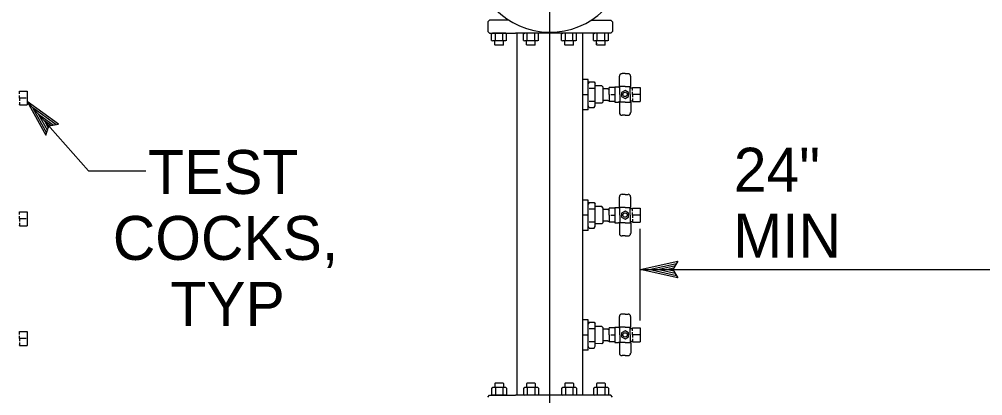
# Model space of a CAD drawing. Extents: x -1680 to 1155, y -802 to 799.
# Drawn here: x 316.4 to 469.8, y -453.1 to -393.2 of the extents above; entities that cross this region are included whole.
import ezdxf

# ---------------------------------------------------------------- set-up
doc = ezdxf.new("R2010")
doc.units = 0
doc.layers.add('Misc CnstDet(22)', color=7, linetype='Continuous')

msp = doc.modelspace()

# ---------------------------------------------------------------- linework, layer by layer
at = {"layer": 'Misc CnstDet(22)'}
for p, q in [((400.86, -548.25), (400.86, -300.3)), ((390.94, -393.62), (391.21, -393.34)), ((390.94, -393.62), (390.94, -395.14)), ((394.3, -393.34), (391.21, -393.34)), ((407.44, -393.34), (410.53, -393.34)), ((410.53, -393.34), (410.8, -393.62)), ((410.8, -393.62), (410.8, -395.14)), ((390.94, -395.14), (391.21, -395.41)), ((391.21, -395.41), (395.35, -395.41)), ((391.56, -395.5), (391.72, -395.41)), ((391.56, -396.56), (391.56, -395.5)), ((393.79, -395.41), (391.72, -395.41)), ((392.16, -396.55), (392.16, -395.51)), ((393.35, -396.55), (393.35, -395.51)), ((393.95, -395.5), (393.79, -395.41)), ((393.95, -396.56), (393.95, -395.5)), ((400.87, -395.41), (395.35, -395.41)), ((395.63, -396.68), (395.63, -395.41)), ((396.64, -395.5), (396.8, -395.41)), ((396.64, -396.56), (396.64, -395.5)), ((398.87, -395.41), (396.8, -395.41)), ((397.23, -396.55), (397.23, -395.51)), ((398.43, -396.55), (398.43, -395.51)), ((399.03, -395.5), (398.87, -395.41)), ((399.03, -396.56), (399.03, -395.5)), ((410.53, -395.41), (400.87, -395.41)), ((402.71, -395.5), (402.87, -395.41)), ((402.71, -396.56), (402.71, -395.5)), ((404.94, -395.41), (402.87, -395.41)), ((403.31, -396.55), (403.31, -395.51)), ((404.51, -396.55), (404.51, -395.51)), ((405.1, -395.5), (404.94, -395.41)), ((405.1, -396.56), (405.1, -395.5)), ((406.11, -396.68), (406.11, -395.41)), ((407.79, -395.5), (407.95, -395.41)), ((407.79, -396.56), (407.79, -395.5)), ((410.02, -395.41), (407.95, -395.41)), ((408.39, -396.55), (408.39, -395.51)), ((409.58, -396.55), (409.58, -395.51)), ((410.18, -395.5), (410.02, -395.41)), ((410.18, -396.56), (410.18, -395.5)), ((410.8, -395.14), (410.53, -395.41)), ((391.56, -396.56), (391.72, -396.65)), ((393.79, -396.65), (391.72, -396.65)), ((392.07, -397.28), (392.07, -396.65)), ((392.13, -397.34), (392.07, -397.28)), ((393.38, -397.34), (393.44, -397.28)), ((393.44, -397.28), (393.44, -396.65)), ((393.95, -396.56), (393.79, -396.65)), ((395.63, -453.08), (395.63, -396.68)), ((396.64, -396.56), (396.8, -396.65)), ((398.87, -396.65), (396.8, -396.65)), ((397.14, -397.28), (397.14, -396.65)), ((397.21, -397.34), (397.14, -397.28)), ((398.46, -397.34), (398.52, -397.28)), ((398.52, -397.28), (398.52, -396.65)), ((399.03, -396.56), (398.87, -396.65)), ((402.71, -396.56), (402.87, -396.65)), ((404.94, -396.65), (402.87, -396.65)), ((403.22, -397.28), (403.22, -396.65)), ((403.28, -397.34), (403.22, -397.28)), ((404.53, -397.34), (404.6, -397.28)), ((404.6, -397.28), (404.6, -396.65)), ((405.1, -396.56), (404.94, -396.65)), ((406.11, -453.08), (406.11, -396.68)), ((407.79, -396.56), (407.95, -396.65)), ((410.02, -396.65), (407.95, -396.65)), ((408.29, -397.28), (408.29, -396.65)), ((408.36, -397.09), (408.29, -397.02)), ((408.36, -397.34), (408.29, -397.28)), ((409.61, -397.34), (409.67, -397.28)), ((409.67, -397.28), (409.67, -396.65)), ((410.18, -396.56), (410.02, -396.65)), ((393.38, -397.34), (392.13, -397.34)), ((398.46, -397.34), (397.21, -397.34)), ((404.53, -397.34), (403.28, -397.34)), ((409.61, -397.34), (408.36, -397.34)), ((412.81, -401.86), (412.33, -401.86)), ((412.81, -401.86), (413.29, -401.86)), ((406.94, -402.79), (406.11, -402.79)), ((406.94, -407.62), (406.94, -402.79)), ((407.1, -403.15), (406.94, -403.42)), ((407.1, -403.15), (407.88, -403.15)), ((407.88, -403.15), (408.04, -403.42)), ((407.97, -403.28), (408.04, -403.41)), ((408.04, -406.99), (408.04, -403.41)), ((408.04, -406.99), (408.04, -403.41)), ((411.92, -403.93), (411.92, -402.28)), ((413.71, -403.93), (413.71, -402.28)), ((316.39, -405.1), (316.39, -404.64)), ((316.39, -404.64), (317.61, -404.64)), ((317.61, -404.64), (317.61, -405.75)), ((407.1, -404.16), (407.88, -404.16)), ((409.11, -403.82), (408.04, -403.82)), ((409.33, -404.04), (409.11, -403.82)), ((409.33, -406.36), (409.33, -404.04)), ((409.54, -404.27), (409.33, -404.28)), ((410.09, -404.27), (409.54, -404.27)), ((410.09, -404.27), (410.3, -404.28)), ((410.3, -405.17), (410.3, -404.07)), ((411.21, -404.07), (410.3, -404.07)), ((410.41, -404.38), (410.41, -404.38)), ((411.21, -404.07), (411.06, -404.07)), ((411.21, -403.97), (411.21, -406.38)), ((411.21, -403.97), (411.76, -403.97)), ((411.81, -403.97), (411.81, -403.97)), ((411.81, -404.07), (411.81, -404)), ((411.84, -404.02), (411.98, -404.02)), ((412.81, -403.93), (411.92, -403.93)), ((411.98, -405.17), (411.98, -403.93)), ((412.81, -403.93), (413.71, -403.93)), ((413.64, -405.17), (413.64, -403.93)), ((413.65, -404.14), (413.96, -404.14)), ((414, -404.52), (414, -404.07)), ((414, -404.07), (415.22, -404.07)), ((414, -405.17), (414, -404.75)), ((415.22, -404.07), (415.22, -405.17)), ((316.39, -405.75), (316.39, -405.32)), ((316.39, -405.75), (316.39, -406.17)), ((316.39, -406.4), (316.39, -406.85)), ((317.48, -405.75), (316.52, -405.75)), ((317.61, -405.75), (317.61, -406.85)), ((322.59, -409.9), (317.61, -406.3)), ((317.61, -406.3), (317.61, -406.3)), ((317.61, -406.3), (320.59, -411.67)), ((406.94, -405.21), (406.11, -405.21)), ((407.1, -406.24), (407.88, -406.24)), ((409.33, -406.36), (409.11, -406.58)), ((409.54, -406.13), (409.33, -406.12)), ((410.09, -406.13), (409.54, -406.13)), ((410.09, -406.13), (410.3, -406.12)), ((410.3, -405.17), (410.3, -406.28)), ((411.21, -406.28), (410.3, -406.28)), ((410.41, -406.23), (410.41, -406.23)), ((410.55, -405.17), (411.21, -405.17)), ((411.21, -406.38), (411.76, -406.38)), ((411.81, -406.28), (411.81, -406.34)), ((411.84, -406.32), (411.98, -406.32)), ((411.92, -406.41), (411.92, -408.07)), ((412.81, -406.41), (411.92, -406.41)), ((411.98, -405.17), (411.98, -406.41)), ((412.81, -406.41), (413.71, -406.41)), ((413.64, -405.17), (413.64, -406.41)), ((413.65, -406.21), (413.96, -406.21)), ((413.71, -406.41), (413.71, -408.07)), ((414, -405.17), (414, -405.6)), ((414, -405.82), (414, -406.28)), ((414, -406.28), (415.22, -406.28)), ((415.09, -405.17), (414.13, -405.17)), ((415.22, -405.17), (415.22, -406.28)), ((316.39, -406.85), (317.61, -406.85)), ((322.18, -409.98), (318.53, -407.33)), ((318.53, -407.34), (320.7, -411.26)), ((406.94, -407.62), (406.11, -407.62)), ((407.1, -407.27), (406.94, -406.99)), ((407.1, -407.27), (407.88, -407.27)), ((407.88, -407.27), (408.04, -406.99)), ((409.11, -406.58), (408.04, -406.58)), ((321.76, -410.04), (319.44, -408.37)), ((319.44, -408.37), (320.85, -410.9)), ((321.38, -410.14), (320.36, -409.4)), ((320.36, -409.4), (320.96, -410.48)), ((412.81, -408.48), (412.33, -408.48)), ((412.81, -408.48), (413.29, -408.48)), ((320.59, -411.67), (321.06, -410.19)), ((321.06, -410.19), (322.59, -409.9)), ((322.59, -409.9), (322.59, -409.9)), ((320.59, -411.67), (320.59, -411.67)), ((411.92, -423.15), (411.92, -421.49)), ((412.81, -421.08), (412.33, -421.08)), ((412.81, -421.08), (413.29, -421.08)), ((413.71, -423.15), (413.71, -421.49)), ((406.94, -422.01), (406.11, -422.01)), ((406.94, -426.84), (406.94, -422.01)), ((407.1, -422.36), (406.94, -422.64)), ((407.1, -422.36), (407.88, -422.36)), ((407.1, -423.38), (407.88, -423.38)), ((407.88, -422.36), (408.04, -422.64)), ((407.97, -422.49), (408.04, -422.62)), ((408.04, -426.21), (408.04, -422.62)), ((408.04, -426.21), (408.04, -422.62)), ((409.11, -423.04), (408.04, -423.04)), ((409.33, -423.26), (409.11, -423.04)), ((409.33, -425.57), (409.33, -423.26)), ((410.3, -424.39), (410.3, -423.29)), ((411.21, -423.29), (410.3, -423.29)), ((411.21, -423.29), (411.06, -423.29)), ((411.21, -423.18), (411.21, -425.59)), ((411.21, -423.18), (411.76, -423.18)), ((411.81, -423.18), (411.81, -423.18)), ((411.81, -423.29), (411.81, -423.22)), ((411.84, -423.24), (411.98, -423.24)), ((412.81, -423.15), (411.92, -423.15)), ((411.98, -424.39), (411.98, -423.15)), ((412.81, -423.15), (413.71, -423.15)), ((413.64, -424.39), (413.64, -423.15)), ((413.65, -423.35), (413.96, -423.35)), ((414, -423.74), (414, -423.29)), ((414, -423.29), (415.22, -423.29)), ((415.22, -423.29), (415.22, -424.39)), ((316.39, -424.31), (316.39, -423.86)), ((316.39, -423.86), (317.61, -423.86)), ((316.39, -424.96), (316.39, -424.54)), ((317.61, -423.86), (317.61, -424.96)), ((406.94, -424.42), (406.11, -424.42)), ((409.54, -423.49), (409.33, -423.49)), ((410.09, -423.49), (409.54, -423.49)), ((410.09, -423.49), (410.3, -423.49)), ((410.3, -424.39), (410.3, -425.49)), ((410.41, -423.59), (410.41, -423.59)), ((410.55, -424.39), (411.21, -424.39)), ((411.98, -424.39), (411.98, -425.63)), ((413.64, -424.39), (413.64, -425.63)), ((414, -424.39), (414, -423.96)), ((414, -424.39), (414, -424.82)), ((415.09, -424.39), (414.13, -424.39)), ((415.22, -424.39), (415.22, -425.49)), ((316.39, -424.96), (316.39, -425.39)), ((316.39, -425.62), (316.39, -426.07)), ((316.39, -426.07), (317.61, -426.07)), ((317.48, -424.96), (316.52, -424.96)), ((317.61, -424.96), (317.61, -426.07)), ((407.1, -426.49), (406.94, -426.21)), ((407.1, -425.45), (407.88, -425.45)), ((407.88, -426.49), (408.04, -426.21)), ((409.11, -425.79), (408.04, -425.79)), ((409.33, -425.57), (409.11, -425.79)), ((409.54, -425.34), (409.33, -425.34)), ((410.09, -425.34), (409.54, -425.34)), ((410.09, -425.34), (410.3, -425.34)), ((411.21, -425.49), (410.3, -425.49)), ((410.41, -425.45), (410.41, -425.45)), ((411.21, -425.59), (411.76, -425.59)), ((411.81, -425.49), (411.81, -425.56)), ((411.84, -425.54), (411.98, -425.54)), ((411.92, -425.63), (411.92, -427.29)), ((412.81, -425.63), (411.92, -425.63)), ((412.81, -425.63), (413.71, -425.63)), ((413.65, -425.42), (413.96, -425.42)), ((413.71, -425.63), (413.71, -427.29)), ((414, -425.04), (414, -425.49)), ((414, -425.49), (415.22, -425.49)), ((406.94, -426.84), (406.11, -426.84)), ((407.1, -426.49), (407.88, -426.49)), ((412.81, -427.7), (412.33, -427.7)), ((412.81, -427.7), (413.29, -427.7)), ((415.24, -441.19), (415.24, -426.57)), ((415.24, -433.05), (421.24, -431.72)), ((416.63, -433.05), (421.01, -432.08)), ((418, -433.05), (420.83, -432.43)), ((421.24, -431.72), (420.44, -433.05)), ((421.24, -431.72), (421.24, -431.72)), ((421.24, -434.39), (415.24, -433.05)), ((415.24, -433.05), (415.24, -433.05)), ((415.24, -433.05), (478.93, -433.05)), ((421.02, -434.03), (416.62, -433.05)), ((420.79, -433.67), (418, -433.05)), ((419.38, -433.05), (420.59, -432.79)), ((420.61, -433.33), (419.38, -433.05)), ((420.44, -433.05), (421.24, -434.39)), ((421.24, -434.39), (421.24, -434.39)), ((412.81, -440.14), (412.33, -440.14)), ((412.81, -440.14), (413.29, -440.14)), ((406.94, -441.07), (406.11, -441.07)), ((406.94, -445.9), (406.94, -441.07)), ((407.1, -441.42), (406.94, -441.7)), ((407.1, -441.42), (407.88, -441.42)), ((407.88, -441.42), (408.04, -441.7)), ((407.97, -441.56), (408.04, -441.68)), ((408.04, -445.27), (408.04, -441.68)), ((408.04, -445.27), (408.04, -441.68)), ((411.92, -442.21), (411.92, -440.55)), ((413.71, -442.21), (413.71, -440.55)), ((316.39, -443.37), (316.39, -442.92)), ((316.39, -442.92), (317.61, -442.92)), ((317.61, -442.92), (317.61, -444.03)), ((407.1, -442.44), (407.88, -442.44)), ((409.11, -442.1), (408.04, -442.1)), ((409.33, -442.32), (409.11, -442.1)), ((409.33, -444.64), (409.33, -442.32)), ((409.54, -442.55), (409.33, -442.56)), ((410.09, -442.55), (409.54, -442.55)), ((410.09, -442.55), (410.3, -442.56)), ((410.3, -443.45), (410.3, -442.35)), ((411.21, -442.35), (410.3, -442.35)), ((410.41, -442.66), (410.41, -442.66)), ((411.21, -442.35), (411.06, -442.35)), ((411.21, -442.25), (411.21, -444.65)), ((411.21, -442.25), (411.76, -442.25)), ((411.81, -442.25), (411.81, -442.25)), ((411.81, -442.35), (411.81, -442.28)), ((411.84, -442.3), (411.98, -442.3)), ((412.81, -442.21), (411.92, -442.21)), ((411.98, -443.45), (411.98, -442.21)), ((412.81, -442.21), (413.71, -442.21)), ((413.64, -443.45), (413.64, -442.21)), ((413.65, -442.42), (413.96, -442.42)), ((414, -442.8), (414, -442.35)), ((414, -442.35), (415.22, -442.35)), ((414, -443.45), (414, -443.02)), ((415.22, -442.35), (415.22, -443.45)), ((316.39, -444.03), (316.39, -443.6)), ((316.39, -444.03), (316.39, -444.45)), ((316.39, -444.68), (316.39, -445.13)), ((317.48, -444.03), (316.52, -444.03)), ((317.61, -444.03), (317.61, -445.13)), ((406.94, -443.49), (406.11, -443.49)), ((407.1, -444.51), (407.88, -444.51)), ((409.11, -444.86), (408.04, -444.85)), ((409.33, -444.64), (409.11, -444.86)), ((409.54, -444.4), (409.33, -444.4)), ((410.09, -444.4), (409.54, -444.4)), ((410.09, -444.4), (410.3, -444.4)), ((410.3, -443.45), (410.3, -444.55)), ((411.21, -444.55), (410.3, -444.55)), ((410.41, -444.51), (410.41, -444.51)), ((410.55, -443.45), (411.21, -443.45)), ((411.21, -444.65), (411.76, -444.65)), ((411.81, -444.55), (411.81, -444.62)), ((411.84, -444.6), (411.98, -444.6)), ((411.92, -444.69), (411.92, -446.35)), ((412.81, -444.69), (411.92, -444.69)), ((411.98, -443.45), (411.98, -444.69)), ((412.81, -444.69), (413.71, -444.69)), ((413.64, -443.45), (413.64, -444.69)), ((413.65, -444.48), (413.96, -444.48)), ((413.71, -444.69), (413.71, -446.35)), ((414, -443.45), (414, -443.88)), ((414, -444.1), (414, -444.55)), ((414, -444.55), (415.22, -444.55)), ((415.09, -443.45), (414.13, -443.45)), ((415.22, -443.45), (415.22, -444.55)), ((316.39, -445.13), (317.61, -445.13)), ((406.94, -445.9), (406.11, -445.9)), ((407.1, -445.55), (406.94, -445.27)), ((407.1, -445.55), (407.88, -445.55)), ((407.88, -445.55), (408.04, -445.27)), ((412.81, -446.76), (412.33, -446.76)), ((412.81, -446.76), (413.29, -446.76)), ((391.56, -451.93), (391.72, -451.84)), ((391.56, -451.93), (391.56, -452.98)), ((393.79, -451.84), (391.72, -451.84)), ((392.13, -451.15), (392.07, -451.21)), ((392.07, -451.21), (392.07, -451.84)), ((393.38, -451.15), (392.13, -451.15)), ((392.16, -451.94), (392.16, -452.98)), ((393.35, -451.94), (393.35, -452.98)), ((393.38, -451.15), (393.44, -451.21)), ((393.44, -451.21), (393.44, -451.84)), ((393.95, -451.93), (393.79, -451.84)), ((393.95, -451.93), (393.95, -452.98)), ((396.64, -451.93), (396.8, -451.84)), ((396.64, -451.93), (396.64, -452.98)), ((398.87, -451.84), (396.8, -451.84)), ((397.21, -451.15), (397.14, -451.21)), ((397.14, -451.21), (397.14, -451.84)), ((398.46, -451.15), (397.21, -451.15)), ((397.23, -451.94), (397.23, -452.98)), ((398.43, -451.94), (398.43, -452.98)), ((398.46, -451.15), (398.52, -451.21)), ((398.52, -451.21), (398.52, -451.84)), ((399.03, -451.93), (398.87, -451.84)), ((399.03, -451.93), (399.03, -452.98)), ((402.71, -451.93), (402.87, -451.84)), ((402.71, -451.93), (402.71, -452.98)), ((404.94, -451.84), (402.87, -451.84)), ((403.28, -451.15), (403.22, -451.21)), ((403.22, -451.21), (403.22, -451.84)), ((404.53, -451.15), (403.28, -451.15)), ((403.31, -451.94), (403.31, -452.98)), ((404.51, -451.94), (404.51, -452.98)), ((404.53, -451.15), (404.6, -451.21)), ((404.6, -451.21), (404.6, -451.84)), ((405.1, -451.93), (404.94, -451.84)), ((405.1, -451.93), (405.1, -452.98)), ((407.79, -451.93), (407.95, -451.84)), ((407.79, -451.93), (407.79, -452.98)), ((410.02, -451.84), (407.95, -451.84)), ((408.36, -451.15), (408.29, -451.21)), ((408.29, -451.21), (408.29, -451.84)), ((409.61, -451.15), (408.36, -451.15)), ((408.39, -451.94), (408.39, -452.98)), ((409.58, -451.94), (409.58, -452.98)), ((409.61, -451.15), (409.67, -451.21)), ((409.67, -451.21), (409.67, -451.84)), ((410.18, -451.93), (410.02, -451.84)), ((410.18, -451.93), (410.18, -452.98)), ((390.94, -453.35), (391.21, -453.08)), ((391.21, -453.08), (395.35, -453.08)), ((391.56, -452.98), (391.72, -453.08)), ((393.79, -453.08), (391.72, -453.08)), ((393.95, -452.98), (393.79, -453.08)), ((410.53, -453.08), (395.35, -453.08)), ((396.64, -452.98), (396.8, -453.08)), ((398.87, -453.08), (396.8, -453.08)), ((399.03, -452.98), (398.87, -453.08)), ((402.71, -452.98), (402.87, -453.08)), ((404.94, -453.08), (402.87, -453.08)), ((405.1, -452.98), (404.94, -453.08)), ((407.79, -452.98), (407.95, -453.08)), ((410.02, -453.08), (407.95, -453.08)), ((410.18, -452.98), (410.02, -453.08)), ((410.8, -453.35), (410.53, -453.08))]:
    msp.add_line(p, q, dxfattribs=at)
for points in [[(412.26, -405.49), (412.81, -405.81), (413.36, -405.49), (413.36, -404.85), (412.81, -404.54), (412.26, -404.85)], [(412.26, -424.71), (412.81, -425.03), (413.36, -424.71), (413.36, -424.07), (412.81, -423.75), (412.26, -424.07)], [(412.26, -443.77), (412.81, -444.09), (413.36, -443.77), (413.36, -443.13), (412.81, -442.81), (412.26, -443.13)]]:
    msp.add_lwpolyline(points, close=True, dxfattribs=at)
msp.add_lwpolyline([(317.61, -406.3), (327.4, -417.36), (336.53, -417.36)], dxfattribs=at)
for centre in [(412.81, -405.17), (412.81, -424.39), (412.81, -443.45)]:
    msp.add_circle(centre, 0.345, dxfattribs=at)
for centre, radius, start, end in [((400.87, -383.13), 12.14, 89.4109, 89.3632), ((412.33, -402.28), 0.414, 90, 180), ((413.29, -402.28), 0.414, 0, 90), ((316.36, -404.68), 0.0345, 270, 0), ((411.76, -404.02), 0.0482, 27.2796, 90), ((411.84, -403.97), 0.0482, 207.2796, 270), ((413.65, -404.1), 0.0345, 254.1733, 270), ((413.96, -404.1), 0.0345, 270, 0), ((411.76, -406.33), 0.0482, 270, 332.7204), ((411.84, -406.37), 0.0482, 90, 152.7204), ((413.96, -406.24), 0.0345, 0, 90), ((316.36, -406.82), 0.0345, 0, 90), ((412.33, -408.07), 0.414, 180, 270), ((413.29, -408.07), 0.414, 270, 0), ((412.33, -421.49), 0.414, 90, 180), ((413.29, -421.49), 0.414, 0, 90), ((411.76, -423.23), 0.0482, 27.2796, 90), ((411.84, -423.19), 0.0482, 207.2796, 270), ((413.65, -423.32), 0.0345, 254.1733, 270), ((413.96, -423.32), 0.0345, 270, 0), ((316.36, -423.89), 0.0345, 270, 0), ((316.36, -426.03), 0.0345, 0, 90), ((411.76, -425.54), 0.0482, 270, 332.7204), ((411.84, -425.59), 0.0482, 90, 152.7204), ((413.96, -425.46), 0.0345, 0, 90), ((412.33, -427.29), 0.414, 180, 270), ((413.29, -427.29), 0.414, 270, 0), ((412.33, -440.55), 0.414, 90, 180), ((413.29, -440.55), 0.414, 0, 90), ((316.36, -442.96), 0.0345, 270, 0), ((411.76, -442.29), 0.0482, 27.2796, 90), ((411.84, -442.25), 0.0482, 207.2796, 270), ((413.65, -442.38), 0.0345, 254.1733, 270), ((413.96, -442.38), 0.0345, 270, 0), ((411.76, -444.61), 0.0482, 270, 332.7204), ((411.84, -444.65), 0.0482, 90, 152.7204), ((413.96, -444.52), 0.0345, 0, 90), ((316.36, -445.09), 0.0345, 0, 90), ((412.33, -446.35), 0.414, 180, 270), ((413.29, -446.35), 0.414, 270, 0)]:
    msp.add_arc(centre, radius, start, end, dxfattribs=at)

# ---------------------------------------------------------------- texts
for s, p in [('TEST', (336.87, -421.02)), ('24"', (430.13, -420.66)), ('COCKS,', (331.25, -431.52)), ('MIN', (430.04, -431.16)), ('TYP', (340.43, -442.02))]:
    msp.add_text(s, height=7, dxfattribs=at).set_placement(p)

doc.saveas('drawing.dxf')
